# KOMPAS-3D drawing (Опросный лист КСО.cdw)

Views: Вид 2
Referenced files in C:\Users\PetrovAY\AppData\Local\Microsoft\Windows\INetCache\AppData\Local\Microsoft\Windows\Temporary Internet Files\Content.Outlook\HMVEOLHC\: LOGO_СВЭЛ.PNG
Referenced files in E:\КТПП\3ЭТ.020.304.026\001\: 3ЭТ.020.304.026-001 Э.CDW
Referenced files in C:\Users\PetrovAY\Desktop\: 1.cdw
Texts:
  133 1 134 1 135 1 136 0 50 1|SPDS|133 1 134 1 135 1 136 0 50 1
  125 1 126 1 127 1 128 0 50 1|SPDS|125 1 126 1 127 1 128 0 50 1
  129 1 130 1 131 1 132 0 50 1|SPDS|129 1 130 1 131 1 132 0 50 1
  Локальный фрагмент 1
  ШОЛ СВЭЛ У3
  HGM250H
  UPB630S
  HGM125H
  HGM50H
  Регул.
  Электронный
  выносн. повор.
  ТТИ-А, кл. 0,5S
  ТТИ, кл. 0,5S
  ПСЧ-4ТМ.05МК.04
  ШОС СВЭЛ У3
  HGS10A
  GPR-LP
  Моторный
  Секционный выключатель
  УКРМ
  Резерв
  ESK - Обозначение
  Normal
  Лит-Масса-Масштаб
  Материал-Предприятие
  Порядковый номер камеры
  Серия камер
  Номинальное напряжение, кВ
  Номинальный ток сборных шин, А
  Материал сборных шин
  Значение и вид оперативного тока
  Схема главных цепей
  Назначение камеры
  Обозначение схемы главных цепей
  Номинальный ток главных цепей камеры, А
  Тип коммутационного аппарата
  Блокировка КА
  Блокировка заземлителя
  Без блокировки
  Электромагнитная
  Замковая
  Номинальный ток предохранителя, А
  Трансформатор напряжения
  Тип
  Трансформатор тока
  Трансформатор тока нулевой последовательности
  Счетчик
  ОПН
  Тип микропроцессорного устройства
  План расположения камер КСО-СВЭЛ-К-1.2
  1. Номинальный ток электродинамической стойкости, кА - ___.
  2. Ток термической стойкости (кратковременный ток), кА - ___.
  3. Степень защиты оболочки по ГОСТ 14254-2015, IP - ____.
  POLYLINE_STYLE_0.18_RGB_0_0_0
  CONTINUOUS_RGB_0_0_255_THICK_0.18
  POLYLINE_STYLE_0.18_RGB_255_0_0
  K5LT32768_RGB_0_0_0_THICK_0.15
  POLYLINE_STYLE_0.30_RGB_0_0_0
  DASHEDX2_RGB_0_0_0_SC_10_THICK_0.09
  ACAD_ISO03W100_RGB_0_0_0_SC_0.05_THICK_0.18
  CONTINUOUS_RGB_0_0_0_THICK_0.15
  K5LT_BASIC_RGB_0_0_255_THICK_0.6
  K5LT_THIN_RGB_0_0_0_THICK_0.18
  POLYLINE_STYLE_18.00_RGB_0_0_0
  K5LT_DASHED_RGB_0_0_0_SC_1_THICK_0.18
  K5LT_AXLED_RGB_255_128_0_SC_1_THICK_0.18
  ANSI33_ISO 1
  КСО-СВЭЛ-К-1.2 У3
  Опросный лист
  Инженер
  ООО "СВЭЛ-СТ"
  г. Екатеринбург
  Нач. ПО
  Нач. ОКТП
  Нач. ОРУБМ
  Рабоч. чертеж зданий и сооруж. ГОСТ Р 21.1101-2009 Ф3.
  Стадия
  Лист
  Листов
  Изм.
  Кол.уч.
  №док.
  Подп.
  Дата
  Изменение
  Номер документа
  Подпись
  Обозначение документа
  Наименование предприятия, в состав которого входит здание (сооружение)
  Наименование здания (сооружения)
  Порядковый номер листа
  Количество листов в документе
  Должность подписавшего
  Наименование изображения
  Индекс предприятия, выпускающего документ
  Инв. № подл.
  Подп. и дата
  Взам. инв. №
  Инвентарный номер подлинника
  Подпись принявшего подлинник на хранение
  Инвентарный номер подлинника, взамен которого выпущен данный подлинник
  Согласовано
  Согласование
  Рабоч. чертеж зданий и сооруж. ГОСТ 21.101-97 Ф3.
  Чертеж строит. Посл. листы. ГОСТ Р 21.1101-2009 Ф6.
  Порядковый номер документа
  Чертеж строит. Посл. листы.  ГОСТ Р 21.1101-2009 Ф6.
Dimensions and other numbers on the sheet: 2/1; 1; 2; 3; 4; 5; 6; 7; 250; 630; 125; 50; 38; 85; 160; 100; 80; 40; 128-160; 320-630; 80-100; 64-80; 32-40; 200-250; 150/5; 500/5; 100/5; 75/5; 40/5; 250/5; 0-150; 0-500; 0-100; 0-75; 0-40; 0-250; 2/2; 2/3; 2/4; 2/5; 2/6; 2/7; 4/2; 1000; 65; 220, 50 Гц; 3/1; 8; 9; 10; 200; 160-200; 100-125; 3/2; 3/3; 5/1; 11; 12; 13; 14; 15; 16; 17; 18; 40-50; 50/5; 0-50; 5/2; 5/3; 5/4; 5/5; 5/6; 5/7; 5/8; 1:1; 3ЭТ.020.304.026-002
